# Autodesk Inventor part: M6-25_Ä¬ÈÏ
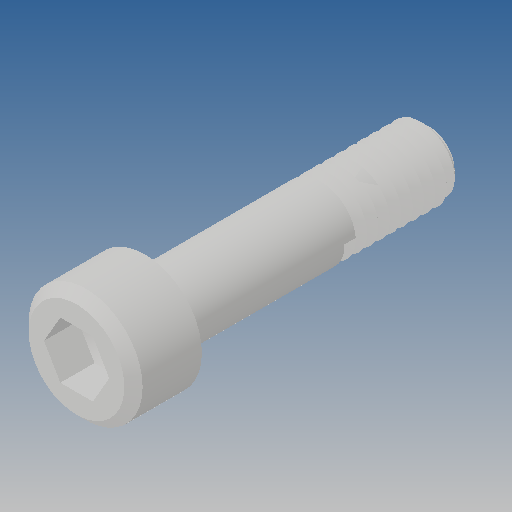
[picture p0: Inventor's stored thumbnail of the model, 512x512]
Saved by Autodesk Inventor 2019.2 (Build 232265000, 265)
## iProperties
Created: 2010-06
Part Number: M6-25_Ä¬ÈÏ
Material: Ogólny
Document SubType Name: Modeling
Designer: CADENGINEERING4
Density: 1 g/cm^3
Appearance: Domyślna
Author: CADENGINEERING4
Revision Number: ÈÎºÎ
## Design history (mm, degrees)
feature "NONE"
node "Bryła1"
